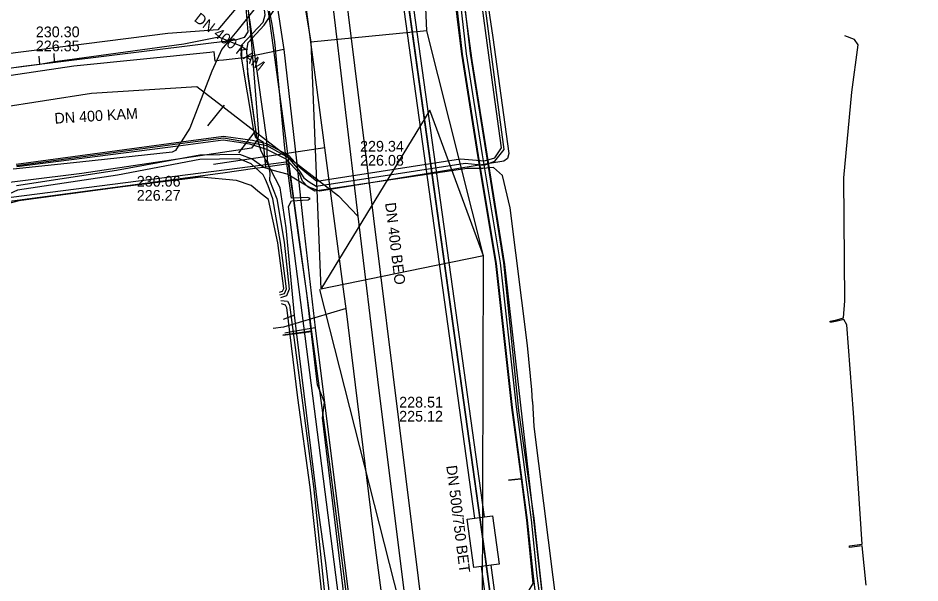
# Model space of a CAD drawing. Extents: x -600309 to -598967, y -1161267 to -1160292.
# Drawn here: x -599150.5 to -599083.1, y -1160621.7 to -1160579.5 of the extents above; entities that cross this region are included whole.
import ezdxf

# ---------------------------------------------------------------- set-up
doc = ezdxf.new("R2010")
doc.units = 0
for name, color, linetype in [('Vrstva 1', 7, 'Continuous'), ('Vrstva 10', 7, 'Continuous'), ('Vrstva 12', 7, 'Continuous'), ('Vrstva 13', 7, 'Continuous'), ('Vrstva 16', 7, 'Continuous'), ('Vrstva 19', 7, 'Continuous'), ('Vrstva 42', 7, 'Continuous'), ('Vrstva 43', 7, 'Continuous'), ('Vrstva 44', 7, 'Continuous'), ('Vrstva 54', 7, 'Continuous'), ('Vrstva 55', 7, 'Continuous'), ('Vrstva 58', 7, 'Continuous'), ('Vrstva 9', 7, 'Continuous')]:
    doc.layers.add(name, color=color, linetype=linetype)

msp = doc.modelspace()

# ---------------------------------------------------------------- linework, layer by layer
at = {"layer": 'Vrstva 1'}
msp.add_lwpolyline([(-599135.125, -1160585.986), (-599136.37, -1160587.53)], dxfattribs=at)
at = {"layer": 'Vrstva 10'}
for points in [[(-599116.39, -1160616.83), (-599127.09, -1160539.91)], [(-599115.67, -1160616.73), (-599126.37, -1160539.82)], [(-599115.9, -1160620.45), (-599116.48, -1160620.53), (-599116.97, -1160616.91), (-599116.39, -1160616.83)], [(-599116.39, -1160616.83), (-599115.67, -1160616.73)], [(-599115.67, -1160616.73), (-599115.08, -1160616.65), (-599114.59, -1160620.27), (-599115.18, -1160620.35)], [(-599115.18, -1160620.35), (-599115.9, -1160620.45)], [(-599103.68, -1160706.7), (-599115.18, -1160620.35)], [(-599104.39, -1160706.8), (-599115.9, -1160620.45)]]:
    msp.add_lwpolyline(points, dxfattribs=at)
at = {"layer": 'Vrstva 12'}
for points in [[(-599126.95, -1160538.17), (-599115.78, -1160618.57)], [(-599132.02, -1160590.61), (-599132.19, -1160588.78), (-599132.77, -1160588.42), (-599132.91, -1160587.88), (-599133.85, -1160582.25), (-599133.8, -1160581.48), (-599132.21, -1160579.79), (-599132.06, -1160579.25), (-599133.9, -1160565.32)], [(-599132.02, -1160590.61), (-599132.84, -1160590.72), (-599135.22, -1160591.06), (-599153.6, -1160593.5), (-599154.04, -1160593.8), (-599154.24, -1160594.55), (-599153.715, -1160599.45)], [(-599129.93, -1160593.11), (-599130.31, -1160590.36), (-599132.02, -1160590.61)], [(-599130.31, -1160590.23), (-599131.23, -1160590.35)], [(-599128.62, -1160602.85), (-599128.95, -1160600.02), (-599129.59, -1160595.53), (-599129.93, -1160593.11)], [(-599130.75, -1160603.13), (-599128.62, -1160602.85)], [(-599125.68, -1160627.01), (-599126.05, -1160624.15), (-599126.05, -1160623.53), (-599127.77, -1160609.34), (-599127.64, -1160608.18), (-599128.15, -1160606.87), (-599128.62, -1160602.85)], [(-599115.78, -1160618.57), (-599103.8, -1160708.41)]]:
    msp.add_lwpolyline(points, dxfattribs=at)
at = {"layer": 'Vrstva 13'}
msp.add_line((-599127.602, -1160589.165), (-599135.921, -1160590.415), dxfattribs=at)
for points in [[(-599121.42, -1160636.85), (-599122.364, -1160629.863), (-599123.9, -1160618.49), (-599126.009, -1160601.164), (-599126.15, -1160600.1), (-599127.602, -1160589.165), (-599130.7, -1160565.824), (-599132.6, -1160551.51), (-599133.796, -1160542.431), (-599135.45, -1160529.95), (-599135.612, -1160528.649), (-599136.039, -1160525.405), (-599136.804, -1160519.607), (-599138.09, -1160509.86), (-599138.528, -1160506.648), (-599138.826, -1160504.459), (-599140.47, -1160492.39), (-599142.053, -1160480.756), (-599142.096, -1160480.442), (-599143.845, -1160467.594), (-599143.98, -1160466.6), (-599144.101, -1160465.516)], [(-599133.81, -1160563.95), (-599132.43, -1160574.65), (-599131.5, -1160581.51), (-599130.55, -1160588.45), (-599130.31, -1160590.23)], [(-599131.23, -1160590.35), (-599154.76, -1160593.36), (-599154.29, -1160596.71)], [(-599130.31, -1160590.23), (-599128.8, -1160601.33)], [(-599126.009, -1160601.164), (-599130.688, -1160602.577), (-599131.463, -1160602.661)], [(-599128.8, -1160601.33), (-599128.59, -1160602.91)], [(-599128.59, -1160602.91), (-599130.74, -1160603.2)], [(-599128.59, -1160602.91), (-599127.28, -1160612.63)], [(-599127.28, -1160612.63), (-599126.76, -1160616.69)], [(-599126.76, -1160616.69), (-599125.02, -1160630.34)]]:
    msp.add_lwpolyline(points, dxfattribs=at)
at = {"layer": 'Vrstva 16'}
for points in [[(-599148.34, -1160450.72), (-599147.26, -1160458.67), (-599144.15, -1160482.57), (-599140.93, -1160506.3), (-599140.83, -1160506.69), (-599140.56, -1160508.63), (-599139.15, -1160519.57), (-599136.15, -1160542.73), (-599133.11, -1160565.88), (-599130.68, -1160581.82), (-599129.71, -1160590.14), (-599129.25, -1160594.55), (-599129.22, -1160594.85), (-599128.33, -1160602.61), (-599124.78, -1160630.94), (-599120.8, -1160661.35), (-599119.1, -1160674.81), (-599115.46, -1160702.27), (-599112.43, -1160726.7), (-599112.19, -1160727.9), (-599111.49, -1160733.02), (-599103, -1160796)], [(-599130.68, -1160581.82), (-599133.66, -1160582.45), (-599135.18, -1160582.62), (-599135.52, -1160582.66)], [(-599135.52, -1160582.66), (-599135.8, -1160582.7), (-599135.87, -1160582.01), (-599136.2, -1160582.05), (-599146.35, -1160583.08), (-599156.59, -1160584.59), (-599157.48, -1160585.94), (-599165.55, -1160587.28), (-599175.48, -1160588.88)], [(-599128.33, -1160602.61), (-599129.94, -1160602.9), (-599130.59, -1160603.02)]]:
    msp.add_lwpolyline(points, dxfattribs=at)
at = {"layer": 'Vrstva 19'}
msp.add_lwpolyline([(-599084.92, -1160929.7), (-599084.859, -1160929.27), (-599083.83, -1160922.03), (-599083.57, -1160912.78), (-599095.07, -1160825.37), (-599102.5, -1160768.3), (-599104.6, -1160752.25), (-599109.62, -1160709.21), (-599119.67, -1160628.93), (-599126.32, -1160575.37), (-599128.11, -1160560.16), (-599133.16, -1160522.31), (-599135.34, -1160510.45), (-599143.35, -1160452.12)], dxfattribs=at)
at = {"layer": 'Vrstva 42'}
for points in [[(-599088.634, -1160791.587), (-599091.432, -1160770.922), (-599096.846, -1160731.939), (-599096.966, -1160730.856), (-599097.779, -1160725.412), (-599098.741, -1160716.448), (-599102.107, -1160691.967), (-599102.783, -1160684.794), (-599106.577, -1160656.83), (-599108.708, -1160639.44), (-599111.325, -1160622.842), (-599114.164, -1160597.877), (-599116.598, -1160582.662), (-599117.768, -1160574.094), (-599118.099, -1160572.56), (-599118.189, -1160569.913), (-599118.731, -1160563.295), (-599122.401, -1160538.48), (-599123.194, -1160531.703), (-599123.577, -1160527.06), (-599123.849, -1160522.402), (-599125.123, -1160512.25), (-599126.606, -1160501.472), (-599128.152, -1160492.134)], [(-599123.799, -1160529.524), (-599122.939, -1160537.799), (-599121.128, -1160550.001), (-599119.309, -1160563.148), (-599118.772, -1160568.478), (-599118.592, -1160571.033), (-599118.553, -1160572.545), (-599118.129, -1160575.16), (-599117.339, -1160582.18), (-599116.138, -1160589.744), (-599114.799, -1160597.801), (-599113.599, -1160608.568), (-599112.479, -1160616.988), (-599112.049, -1160621.167), (-599111.84, -1160622.834), (-599111.578, -1160624.027), (-599110.548, -1160631.141), (-599109.369, -1160639.519), (-599108.299, -1160648.76), (-599107.078, -1160657.081), (-599106.089, -1160664.169)], [(-599123.799, -1160529.524), (-599122.939, -1160537.799), (-599121.128, -1160550.001), (-599119.309, -1160563.148), (-599118.772, -1160568.478), (-599118.592, -1160571.033), (-599118.553, -1160572.545), (-599118.129, -1160575.16), (-599117.339, -1160582.18), (-599116.138, -1160589.744), (-599114.799, -1160597.801), (-599113.599, -1160608.568), (-599112.479, -1160616.988), (-599112.049, -1160621.167), (-599111.84, -1160622.834), (-599111.578, -1160624.027), (-599110.548, -1160631.141), (-599109.369, -1160639.519), (-599108.299, -1160648.76), (-599107.078, -1160657.081), (-599106.089, -1160664.169)], [(-599123.501, -1160529.496), (-599122.641, -1160537.761), (-599120.832, -1160549.959), (-599119.011, -1160563.112), (-599118.474, -1160568.452), (-599118.292, -1160571.019), (-599118.253, -1160572.517), (-599117.831, -1160575.12), (-599117.041, -1160582.14), (-599115.842, -1160589.696), (-599114.501, -1160597.759), (-599113.301, -1160608.532), (-599112.181, -1160616.952), (-599111.751, -1160621.133), (-599111.544, -1160622.778), (-599111.282, -1160623.973), (-599110.252, -1160631.099), (-599109.071, -1160639.481), (-599108.001, -1160648.72), (-599106.782, -1160657.039), (-599105.791, -1160664.131)], [(-599123.501, -1160529.496), (-599122.641, -1160537.761), (-599120.832, -1160549.959), (-599119.011, -1160563.112), (-599118.474, -1160568.452), (-599118.292, -1160571.019), (-599118.253, -1160572.517), (-599117.831, -1160575.12), (-599117.041, -1160582.14), (-599115.842, -1160589.696), (-599114.501, -1160597.759), (-599113.301, -1160608.532), (-599112.181, -1160616.952), (-599111.751, -1160621.133), (-599111.544, -1160622.778), (-599111.282, -1160623.973), (-599110.252, -1160631.099), (-599109.071, -1160639.481), (-599108.001, -1160648.72), (-599106.782, -1160657.039), (-599105.791, -1160664.131)], [(-599121.77, -1160532.77), (-599120.54, -1160541.86), (-599119.38, -1160550.27), (-599118.12, -1160558.96), (-599116.87, -1160568.06), (-599116.04, -1160574.23), (-599115.06, -1160580.93), (-599113.85, -1160589.59), (-599113.96, -1160589.98), (-599114.24, -1160590.16), (-599127.99, -1160592.42), (-599128.81, -1160592.1), (-599130.43, -1160591.15), (-599131.46, -1160590.87), (-599131.764, -1160590.77), (-599132.16, -1160590.64), (-599133.03, -1160590.02), (-599133.96, -1160589.68), (-599136.95, -1160589.72), (-599143.17, -1160590.87), (-599150.64, -1160592.02)], [(-599135.358, -1160567.523), (-599134.875, -1160567.433), (-599134.866, -1160567.52), (-599134.781, -1160568.329), (-599133.905, -1160576.641), (-599133.699, -1160578.099), (-599135.593, -1160580.347), (-599139.337, -1160580.635), (-599162.301, -1160583.552)], [(-599135.31, -1160568.142), (-599135.05, -1160568.25), (-599134.781, -1160568.329), (-599134.573, -1160568.39), (-599133.94, -1160574.22), (-599133.33, -1160578.95), (-599132.9, -1160581.85), (-599131.97, -1160588.55), (-599131.92, -1160590.12), (-599131.8, -1160590.51), (-599131.764, -1160590.77), (-599131.72, -1160591.09), (-599131.73, -1160591.58), (-599131.2, -1160592.98), (-599130.65, -1160596.21), (-599130.265, -1160599.729), (-599130.474, -1160600.217), (-599130.929, -1160600.38)], [(-599119.261, -1160568.554), (-599118.771, -1160568.486), (-599118.474, -1160568.452), (-599118.292, -1160571.019), (-599118.253, -1160572.517), (-599117.831, -1160575.12), (-599117.041, -1160582.14), (-599115.842, -1160589.696), (-599114.501, -1160597.759), (-599113.301, -1160608.532), (-599112.181, -1160616.952), (-599111.751, -1160621.133), (-599111.544, -1160622.778), (-599111.282, -1160623.973), (-599110.252, -1160631.099), (-599109.071, -1160639.481), (-599108.001, -1160648.72), (-599106.782, -1160657.039), (-599105.791, -1160664.131)], [(-599119.261, -1160568.554), (-599118.771, -1160568.486), (-599118.474, -1160568.452), (-599118.292, -1160571.019), (-599118.253, -1160572.517), (-599117.831, -1160575.12), (-599117.041, -1160582.14), (-599115.842, -1160589.696), (-599114.501, -1160597.759), (-599113.301, -1160608.532), (-599112.181, -1160616.952), (-599111.751, -1160621.133), (-599111.544, -1160622.778), (-599111.282, -1160623.973), (-599110.252, -1160631.099), (-599109.071, -1160639.481), (-599108.001, -1160648.72), (-599106.782, -1160657.039), (-599105.791, -1160664.131)], [(-599118.942, -1160571.089), (-599118.592, -1160571.045), (-599118.553, -1160572.545), (-599118.129, -1160575.16), (-599117.339, -1160582.18), (-599116.138, -1160589.744), (-599114.799, -1160597.801), (-599113.599, -1160608.568), (-599112.479, -1160616.988), (-599112.049, -1160621.167), (-599111.84, -1160622.834), (-599111.578, -1160624.027), (-599110.548, -1160631.141), (-599109.369, -1160639.519), (-599108.299, -1160648.76), (-599107.078, -1160657.081), (-599106.089, -1160664.169)], [(-599118.942, -1160571.089), (-599118.592, -1160571.045), (-599118.553, -1160572.545), (-599118.129, -1160575.16), (-599117.339, -1160582.18), (-599116.138, -1160589.744), (-599114.799, -1160597.801), (-599113.599, -1160608.568), (-599112.479, -1160616.988), (-599112.049, -1160621.167), (-599111.84, -1160622.834), (-599111.578, -1160624.027), (-599110.548, -1160631.141), (-599109.369, -1160639.519), (-599108.299, -1160648.76), (-599107.078, -1160657.081), (-599106.089, -1160664.169)], [(-599130.959, -1160600.144), (-599130.62, -1160600.05), (-599130.47, -1160599.7), (-599130.91, -1160596.24), (-599131.48, -1160592.99), (-599131.85, -1160592), (-599132.05, -1160591.54), (-599132.2, -1160591.18), (-599133.11, -1160590.36), (-599134, -1160590), (-599136.95, -1160590.04), (-599143.09, -1160591.22), (-599150.56, -1160592.34), (-599153.64, -1160593.72), (-599153.81, -1160594.16), (-599154.09, -1160594.81), (-599154.25, -1160595.46), (-599153.88, -1160598.03), (-599153.2, -1160603.44), (-599152.588, -1160607.213)], [(-599130.985, -1160599.943), (-599130.766, -1160599.883), (-599130.675, -1160599.671), (-599131.108, -1160596.27), (-599131.82, -1160593.04), (-599132.49, -1160592.52), (-599133.12, -1160591.99), (-599134.21, -1160591.61), (-599136.86, -1160591.37), (-599142.91, -1160592.12), (-599150.48, -1160593.14), (-599153.44, -1160593.91), (-599153.625, -1160594.236), (-599153.77, -1160594.83), (-599153.92, -1160595.42), (-599153.59, -1160597.96), (-599152.86, -1160603.37), (-599152.283, -1160607.161)], [(-599130.904, -1160600.58), (-599130.4, -1160600.62), (-599130.24, -1160600.9), (-599129.32, -1160607.85), (-599128.44, -1160614.47), (-599127.36, -1160625.1)], [(-599130.877, -1160600.791), (-599130.57, -1160600.89), (-599130.48, -1160601.11), (-599129.64, -1160607.86), (-599128.72, -1160614.51), (-599127.56, -1160625.14), (-599126.684, -1160629.734), (-599127.129, -1160629.909), (-599127.189, -1160630.016), (-599127.101, -1160630.098), (-599126.65, -1160630.1), (-599126.2, -1160634.52), (-599124.93, -1160645.26), (-599124.34, -1160650.64), (-599123.73, -1160654.81), (-599123.715, -1160654.995), (-599123.689, -1160655.33), (-599123.677, -1160655.481)]]:
    msp.add_lwpolyline(points, dxfattribs=at)
at = {"layer": 'Vrstva 43'}
for points in [[(-599133.36, -1160583.65), (-599133.43, -1160581.89), (-599133.34, -1160581.31), (-599132.15, -1160580.01), (-599131.32, -1160578.76), (-599130.82, -1160577.37), (-599130.71, -1160577.07), (-599130.78, -1160575.4), (-599131.09, -1160574.4), (-599131.65, -1160573.28), (-599131.84, -1160571.82), (-599131.67, -1160571.41), (-599131.85, -1160568.64), (-599132.2, -1160566.03), (-599133.08, -1160558.69), (-599133.46, -1160557.04), (-599133.99, -1160556.07), (-599134.1, -1160555.58), (-599133.94, -1160554.25), (-599133.6, -1160553.08), (-599134.26, -1160550.91), (-599135.27, -1160543.3), (-599136.81, -1160531.06)], [(-599122.05, -1160662.6), (-599122.13, -1160661.96), (-599122.27, -1160661.35), (-599122.32, -1160660.95), (-599124.2, -1160646.32), (-599124.72, -1160642.54), (-599125.86, -1160634.32), (-599126.14, -1160631.83), (-599126.16, -1160630.81), (-599126.3, -1160630.46), (-599127.53, -1160620.17), (-599128.07, -1160616.26), (-599129.86, -1160601.67), (-599130.5, -1160595.15), (-599130.94, -1160592.17), (-599132.35, -1160589.43), (-599132.68, -1160588.34), (-599133.36, -1160583.65)]]:
    msp.add_lwpolyline(points, dxfattribs=at)
at = {"layer": 'Vrstva 44'}
for points in [[(-599150.67, -1160590.39), (-599138.352, -1160588.729), (-599135.17, -1160588.3), (-599133.02, -1160588.6), (-599131.96, -1160588.85), (-599130.33, -1160589.72), (-599129.54, -1160590.57), (-599129.09, -1160590.95), (-599128.21, -1160591.67), (-599117.46, -1160589.99), (-599115.67, -1160590.14), (-599114.91, -1160589.93), (-599114.41, -1160589.18), (-599114.97, -1160585.01), (-599116.67, -1160572.46), (-599117.15, -1160569.41), (-599117.82, -1160563.59), (-599119.43, -1160551.31), (-599119.8, -1160548.03), (-599120.77, -1160540.29), (-599122.18, -1160530.03)], [(-599150.64, -1160590.5), (-599138.436, -1160588.858), (-599135.18, -1160588.42), (-599133.15, -1160588.77), (-599131.95, -1160588.99), (-599130.34, -1160589.89), (-599129.54, -1160590.85), (-599129.17, -1160591.42), (-599128.78, -1160591.71), (-599128.26, -1160592.03), (-599117.13, -1160590.32), (-599115.7, -1160590.47), (-599114.89, -1160590.16), (-599114.21, -1160589.31), (-599114.78, -1160585.03), (-599116.42, -1160572.42), (-599116.83, -1160569.38), (-599117.56, -1160563.57), (-599119.3, -1160551.01), (-599119.61, -1160548.1), (-599120.52, -1160540.31), (-599121.87, -1160530.11)], [(-599138.52, -1160534.14), (-599137.26, -1160543.9), (-599135.8, -1160554.98), (-599134.51, -1160563.74), (-599133.61, -1160570.59), (-599132.83, -1160575.48), (-599132.57, -1160578.12), (-599132.62, -1160578.48), (-599134.19, -1160580.46), (-599135.3, -1160581.8), (-599136.04, -1160583.44), (-599137.68, -1160587.7), (-599138.352, -1160588.729), (-599138.436, -1160588.858), (-599138.553, -1160589.038), (-599138.77, -1160589.37), (-599139, -1160589.5), (-599145.9, -1160590.25), (-599150.882, -1160590.755)], [(-599112.09, -1160608.13), (-599112.14, -1160607.25), (-599112.47, -1160603.93), (-599113.75, -1160593.66), (-599114.32, -1160591.25), (-599114.999, -1160590.653), (-599115.81, -1160590.71), (-599116.98, -1160590.72), (-599128.35, -1160592.42), (-599128.86, -1160592.12), (-599129.28, -1160591.66), (-599129.5, -1160591.09), (-599130.49, -1160590.02), (-599131.95, -1160589.3), (-599133.2, -1160588.89), (-599135.199, -1160588.604), (-599138.553, -1160589.038), (-599150.62, -1160590.6)], [(-599112.09, -1160608.13), (-599111.98, -1160609.99), (-599109.504, -1160629.736), (-599106.065, -1160655.324), (-599103.642, -1160674.134), (-599100.509, -1160697.439), (-599095.391, -1160735.084), (-599093.34, -1160750.202), (-599089.712, -1160777.364), (-599087.879, -1160792.317), (-599087.434, -1160795.875), (-599084.392, -1160820.684), (-599084.024, -1160822.578), (-599080.74, -1160848.464), (-599078.594, -1160865.22), (-599075.405, -1160890.518), (-599073.694, -1160908.257), (-599072.822, -1160913.918)]]:
    msp.add_lwpolyline(points, dxfattribs=at)
at = {"layer": 'Vrstva 54'}
for points in [[(-599119.99, -1160580.43), (-599120.22, -1160574.7), (-599129.59, -1160575.54), (-599128.64, -1160581.28)], [(-599115.74, -1160597.25), (-599119.99, -1160580.43), (-599128.64, -1160581.28), (-599127.9, -1160599.73)], [(-599115.74, -1160597.25), (-599119.76, -1160586.36), (-599127.9, -1160599.73)], [(-599115.74, -1160597.25), (-599120.37, -1160598.19)], [(-599113.52, -1160643.64), (-599115.162, -1160635.75), (-599115.824, -1160623.989), (-599115.74, -1160597.25)], [(-599120.37, -1160598.19), (-599127.9, -1160599.73)], [(-599120.99, -1160627.88), (-599121.662, -1160624.622), (-599127.969, -1160599.752)]]:
    msp.add_lwpolyline(points, dxfattribs=at)
at = {"layer": 'Vrstva 55'}
for points in [[(-599118.432, -1160573.721), (-599117.388, -1160582.187), (-599116.187, -1160589.752), (-599114.848, -1160597.807), (-599113.649, -1160608.574), (-599112.941, -1160613.899), (-599113.87, -1160613.99), (-599112.941, -1160613.899), (-599112.529, -1160616.993), (-599112.052, -1160621.709), (-599112.368, -1160622.219), (-599112.174, -1160623.605), (-599111.627, -1160624.036), (-599110.598, -1160631.148), (-599109.418, -1160639.525), (-599107.913, -1160651.737), (-599108.59, -1160651.82), (-599107.913, -1160651.737), (-599107.128, -1160657.088), (-599106.138, -1160664.176)], [(-599134.493, -1160575.642), (-599133.901, -1160576.029), (-599133.729, -1160576.573), (-599133.639, -1160577.208), (-599133.36, -1160580.52), (-599133.62, -1160580.94), (-599134.28, -1160581.13), (-599150.15, -1160583.11), (-599164.99, -1160585.19), (-599167.31, -1160584.21), (-599170.11, -1160582.97), (-599180.2, -1160584.21), (-599182.57, -1160584.58), (-599182.83, -1160584.49)], [(-599134.527, -1160575.478), (-599133.799, -1160575.951), (-599133.611, -1160576.547), (-599133.52, -1160577.192), (-599133.14, -1160580.84), (-599132.55, -1160588.03), (-599132.62, -1160588.52), (-599133.09, -1160589.21), (-599145.77, -1160591.1), (-599154, -1160592.11), (-599154.41, -1160592.71), (-599154.22, -1160594.54), (-599153.52, -1160604.46), (-599153.11, -1160609.58), (-599153.416, -1160609.93), (-599162.778, -1160610.887), (-599163.122, -1160610.553), (-599163.19, -1160609.545), (-599163.892, -1160602.284), (-599164.363, -1160601.792), (-599165.925, -1160601.68), (-599167.287, -1160601.545), (-599167.39, -1160601.62)], [(-599120.35, -1160670.81), (-599124.97, -1160634.71), (-599124.757, -1160634.529), (-599123.453, -1160634.271), (-599123.3, -1160634.14), (-599123.491, -1160634.075), (-599124.859, -1160634.314), (-599125.1, -1160634.24), (-599130.33, -1160593.56), (-599130.083, -1160593.131), (-599128.842, -1160593.058), (-599128.69, -1160592.97), (-599128.869, -1160592.878), (-599130.084, -1160592.93), (-599130.6, -1160589.19), (-599131.34, -1160581.26), (-599131.53, -1160579.93), (-599132.2, -1160576.579), (-599132.92, -1160576.05), (-599134.423, -1160575.66)], [(-599087.16, -1160621.84), (-599087.444, -1160618.91), (-599088.392, -1160619.03), (-599088.4, -1160618.97), (-599088.408, -1160618.91), (-599087.454, -1160618.79), (-599087.606, -1160616.524), (-599088.11, -1160608.98), (-599088.6, -1160602.4), (-599088.812, -1160601.984), (-599089.316, -1160602.128), (-599089.828, -1160602.229), (-599089.84, -1160602.17), (-599089.852, -1160602.111), (-599089.344, -1160602.012), (-599088.836, -1160601.866), (-599088.75, -1160600.61), (-599088.82, -1160591.41), (-599088.22, -1160585.01), (-599087.76, -1160581.49), (-599088.03, -1160581.07), (-599088.74, -1160580.81)]]:
    msp.add_lwpolyline(points, dxfattribs=at)
at = {"layer": 'Vrstva 58'}
for points in [[(-599092.6, -1160792.56), (-599099.731, -1160739.009), (-599103.73, -1160708.98), (-599103.87, -1160707.87), (-599112.249, -1160645.022), (-599115.7, -1160619.14), (-599115.86, -1160618.03), (-599124.956, -1160552.58), (-599126.88, -1160538.74), (-599127.03, -1160537.63), (-599136.901, -1160461.461), (-599139.27, -1160443.18), (-599139.39, -1160442.06), (-599141.8, -1160408.22), (-599141.59, -1160407.07), (-599141.37, -1160406.57), (-599141.17, -1160405.42), (-599151.39, -1160306.94), (-599152.04, -1160306.49), (-599167.08, -1160307.6), (-599167.65, -1160307.58), (-599167.66, -1160307.02), (-599167.93, -1160292.347)], [(-599092.6, -1160792.56), (-599099.731, -1160739.009), (-599103.73, -1160708.98), (-599103.87, -1160707.87), (-599112.249, -1160645.022), (-599115.7, -1160619.14), (-599115.86, -1160618.03), (-599124.956, -1160552.58), (-599126.88, -1160538.74), (-599127.03, -1160537.63), (-599136.901, -1160461.461), (-599139.27, -1160443.18), (-599139.39, -1160442.06), (-599141.8, -1160408.22), (-599141.59, -1160407.07), (-599141.37, -1160406.57), (-599141.17, -1160405.42), (-599151.39, -1160306.94), (-599152.04, -1160306.49), (-599167.08, -1160307.6), (-599167.65, -1160307.58), (-599167.66, -1160307.02), (-599167.93, -1160292.347)], [(-599092.6, -1160792.56), (-599099.731, -1160739.009), (-599103.73, -1160708.98), (-599103.87, -1160707.87), (-599112.249, -1160645.022), (-599115.7, -1160619.14), (-599115.86, -1160618.03), (-599124.956, -1160552.58), (-599126.88, -1160538.74), (-599127.03, -1160537.63), (-599136.901, -1160461.461), (-599139.27, -1160443.18), (-599139.39, -1160442.06), (-599141.8, -1160408.22), (-599141.59, -1160407.07), (-599141.37, -1160406.57), (-599141.17, -1160405.42), (-599151.39, -1160306.94), (-599152.04, -1160306.49), (-599167.08, -1160307.6), (-599167.65, -1160307.58), (-599167.66, -1160307.02), (-599167.93, -1160292.347)], [(-599123.358, -1160529.492), (-599122.379, -1160537.892), (-599118.75, -1160563.052), (-599118.22, -1160569.821), (-599118.22, -1160572.39), (-599117.567, -1160575.04), (-599116.752, -1160582.136), (-599114.264, -1160597.753), (-599113.123, -1160608.804), (-599111.981, -1160616.837), (-599111.328, -1160622.75), (-599111.084, -1160623.932), (-599108.76, -1160639.469), (-599105.538, -1160664.18), (-599103.866, -1160677.84), (-599102.724, -1160684.894), (-599102.194, -1160692.112), (-599100.156, -1160707.037), (-599098.728, -1160716.538), (-599097.79, -1160725.59), (-599096.853, -1160731.34), (-599093.427, -1160756.051), (-599089.92, -1160782.393)], [(-599133.43, -1160581.89), (-599133.34, -1160581.31), (-599132.15, -1160580.01), (-599131.32, -1160578.76), (-599130.817, -1160577.367)], [(-599133.36, -1160583.65), (-599133.43, -1160581.89), (-599133.34, -1160581.31), (-599132.15, -1160580.01), (-599131.32, -1160578.76), (-599130.82, -1160577.37)], [(-599148.9, -1160582.94), (-599159.15, -1160584.28), (-599162.61, -1160584.78), (-599163.38, -1160579.71), (-599165.8, -1160580.08), (-599167.373, -1160580.317), (-599172.54, -1160580.96)], [(-599133.43, -1160581.89), (-599133.93, -1160581.56), (-599135.53, -1160580.9), (-599138.147, -1160581.424), (-599146.87, -1160582.62), (-599147.81, -1160582.74)], [(-599129.86, -1160601.67), (-599130.5, -1160595.15), (-599130.94, -1160592.17), (-599132.35, -1160589.43), (-599132.68, -1160588.34), (-599133.368, -1160583.46), (-599133.43, -1160581.89)], [(-599148.9, -1160582.94), (-599148.958, -1160582.337)], [(-599147.81, -1160582.74), (-599147.831, -1160582.138)], [(-599147.81, -1160582.74), (-599148.9, -1160582.94)], [(-599122.05, -1160662.6), (-599122.13, -1160661.96), (-599122.27, -1160661.35), (-599122.32, -1160660.95), (-599124.2, -1160646.32), (-599124.72, -1160642.54), (-599125.86, -1160634.32), (-599126.14, -1160631.83), (-599126.16, -1160630.81), (-599126.3, -1160630.46), (-599127.53, -1160620.17), (-599128.07, -1160616.26), (-599129.86, -1160601.67), (-599130.5, -1160595.15), (-599130.94, -1160592.17), (-599132.35, -1160589.43), (-599132.68, -1160588.34), (-599133.36, -1160583.65)], [(-599129.86, -1160601.67), (-599130.72, -1160602)], [(-599126.3, -1160630.46), (-599127.53, -1160620.17), (-599128.07, -1160616.26), (-599129.86, -1160601.67)]]:
    msp.add_lwpolyline(points, dxfattribs=at)
at = {"layer": 'Vrstva 9'}
for p, q in [((-599128.98, -1160562), (-599125.15, -1160594.285)), ((-599145.04, -1160585.08), (-599137.17, -1160584.59)), ((-599163.19, -1160587.91), (-599145.04, -1160585.08)), ((-599134.034, -1160589.542), (-599132.811, -1160587.96)), ((-599126.59, -1160592.77), (-599125.15, -1160594.285)), ((-599125.15, -1160594.285), (-599123.68, -1160606.47)), ((-599123.68, -1160606.47), (-599118.08, -1160651.07))]:
    msp.add_line(p, q, dxfattribs=at)
msp.add_lwpolyline([(-599137.17, -1160584.59), (-599134.994, -1160586.272), (-599132.811, -1160587.96), (-599126.59, -1160592.77)], dxfattribs=at)

# ---------------------------------------------------------------- texts
at = {"layer": 'Vrstva 12'}
for s, rotation, p in [('DN 400 KAM', 322.28876, (-599137.43, -1160579.653)), ('DN 400 KAM', 3.55234, (-599147.782, -1160587.372)), ('DN 400 BEO', 276.85321, (-599123.105, -1160593.303)), ('DN 500/750 BET', 277.13969, (-599118.534, -1160612.934))]:
    msp.add_text(s, height=0.8, rotation=rotation, dxfattribs=at).set_placement(p)
for s, p in [('230.30', (-599149.201, -1160580.912)), ('226.35', (-599149.201, -1160581.962)), ('229.34', (-599124.971, -1160589.455)), ('226.08', (-599124.971, -1160590.505)), ('230.06', (-599141.656, -1160592.072)), ('226.27', (-599141.656, -1160593.122)), ('228.51', (-599122.049, -1160608.571)), ('225.12', (-599122.049, -1160609.621))]:
    msp.add_text(s, height=0.8, dxfattribs=at).set_placement(p)

doc.saveas('drawing.dxf')
